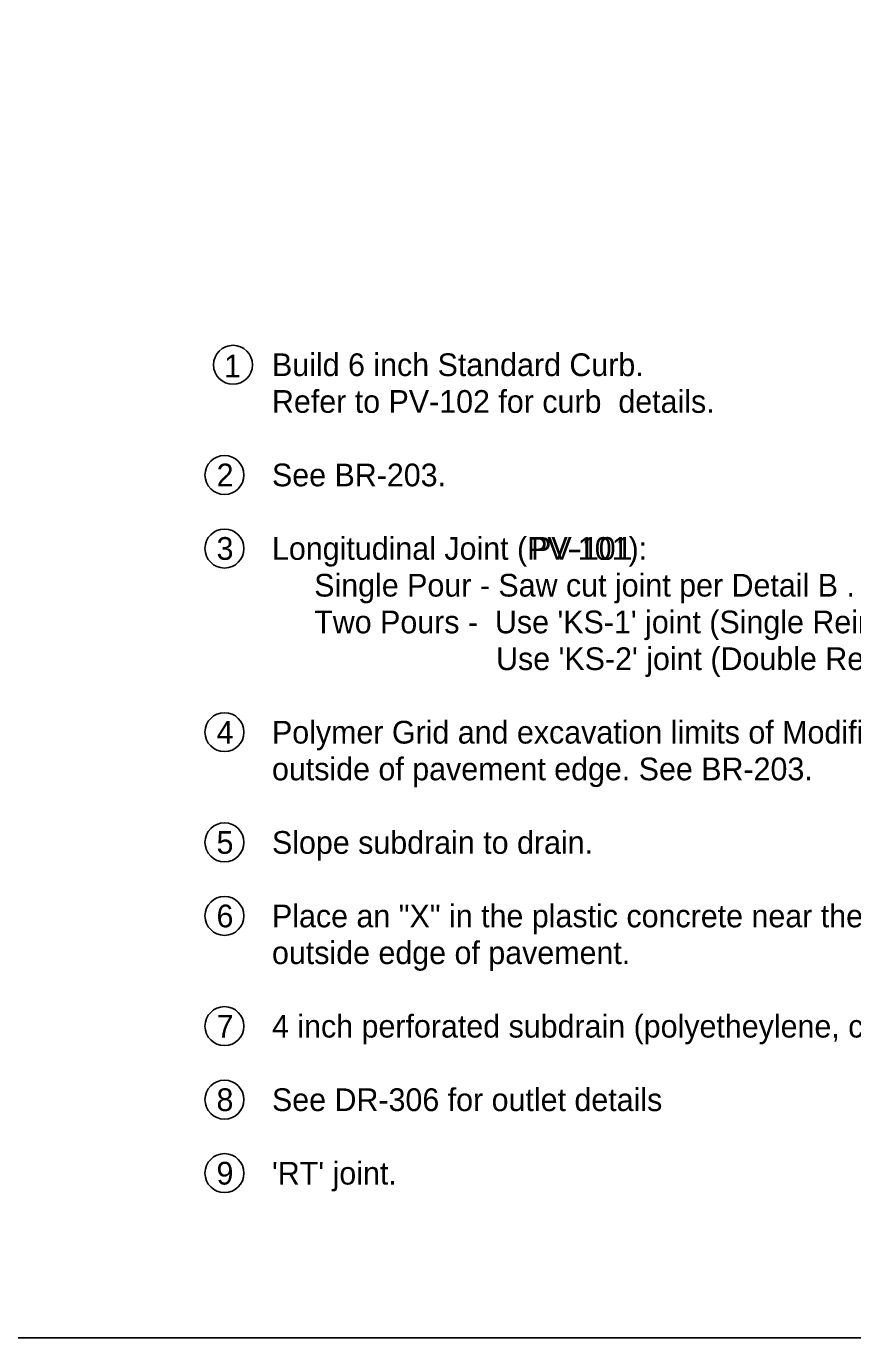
# Model space of a CAD drawing. Extents: x 10133 to 81668, y 7924 to 11018.
# Drawn here: x 11586 to 12222, y 7924 to 8934 of the extents above; entities that cross this region are included whole.
import ezdxf

# ---------------------------------------------------------------- set-up
doc = ezdxf.new("R2010")
doc.units = 0
for name, color, linetype in [('BridgeExistingStructure', 7, 'Continuous'), ('RasterAttachment', 7, 'Continuous'), ('SheetBorder', 7, 'Continuous')]:
    doc.layers.add(name, color=color, linetype=linetype)

msp = doc.modelspace()

# ---------------------------------------------------------------- linework, layer by layer
at = {"layer": 'RasterAttachment'}
for centre in [(11744.9, 8673.3), (11738.3, 8588.4), (11738.3, 8531.8), (11738.3, 8390.4), (11738.3, 8305.5), (11738.3, 8248.9), (11738.3, 8164), (11738.3, 8107.4), (11738.3, 8050.8)]:
    msp.add_circle(centre, 15, dxfattribs=at)
at = {"layer": 'SheetBorder'}
msp.add_lwpolyline([(10132.5, 9944), (13267.5, 9944), (13267.5, 7924), (10132.5, 7924)], close=True, dxfattribs=at)

# ---------------------------------------------------------------- texts
at = {"layer": 'BridgeExistingStructure'}
for s, p in [('1', (11738, 8663.6)), ('Build 6 inch Standard Curb.', (11774.9, 8664.6)), ('Refer to PV-102 for curb  details.', (11774.9, 8636.3)), ('2', (11732.3, 8579.7)), ('See BR-203.', (11774.9, 8579.7)), ('3', (11732.2, 8523.1)), ('Longitudinal Joint (PV-101):', (11774.9, 8523.1)), ('PV-101', (11974.4, 8523.1)), ('     Single Pour - Saw cut joint per Detail B .', (11774.9, 8494.8)), ("     Two Pours -  Use 'KS-1' joint (Single Reinforced Section).", (11774.9, 8466.5)), ("     Use 'KS-2' joint (Double Reinforced Section).", (11914.9, 8438.2)), ('4', (11732.2, 8381.6)), ('Polymer Grid and excavation limits of Modified Subbase 2 feet ', (11774.9, 8381.6)), ('outside of pavement edge. See BR-203.', (11774.9, 8353.3)), ('5', (11732.2, 8296.7)), ('Slope subdrain to drain.', (11774.9, 8296.7)), ('6', (11732.2, 8240.1)), ('Place an "X" in the plastic concrete near the \'EF\' joint at the ', (11774.9, 8240.1)), ('outside edge of pavement.', (11774.9, 8211.8)), ('7', (11732.3, 8155.2)), ('4 inch perforated subdrain (polyetheylene, corrugated tubing).', (11774.9, 8155.2)), ('8', (11732.2, 8098.6)), ('See DR-306 for outlet details', (11774.9, 8098.6)), ("'RT' joint.", (11774.9, 8042)), ('9', (11732.2, 8042))]:
    msp.add_text(s, height=17.5, dxfattribs=at).set_placement(p)

doc.saveas('drawing.dxf')
